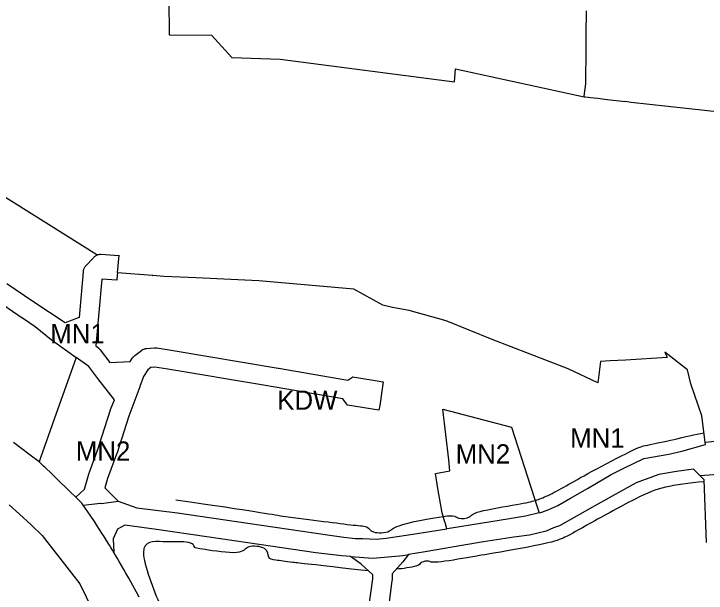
# Model space of a CAD drawing. Extents: x 7413438 to 7416393, y 5541665 to 5544118.
# Drawn here: x 7414826.9 to 7415042.1, y 5542227.9 to 5542408 of the extents above; entities that cross this region are included whole.
import ezdxf

# ---------------------------------------------------------------- set-up
doc = ezdxf.new("R2010")
doc.units = 0
for name, color, linetype in [('linie_rozgraniczajace', 7, 'Continuous'), ('linie_zabudowy_nieprzekraczalne', 7, 'Continuous'), ('oznaczenia_przeznaczen', 7, 'Continuous')]:
    doc.layers.add(name, color=color, linetype=linetype)

msp = doc.modelspace()

# ---------------------------------------------------------------- linework, layer by layer
at = {"layer": 'linie_rozgraniczajace'}
for p, q in [((7414875.1, 5542412.57), (7414875.21, 5542401.44)), ((7415004.88, 5542406.23), (7415004.9, 5542409)), ((7415004.87, 5542404.29), (7415004.88, 5542406.23)), ((7415004.86, 5542402.09), (7415004.87, 5542404.29)), ((7414875.21, 5542401.44), (7414888.35, 5542401.42)), ((7414888.35, 5542401.42), (7414894.65, 5542394.42)), ((7415004.82, 5542397.73), (7415004.86, 5542402.09)), ((7415004.79, 5542393.86), (7415004.82, 5542397.73)), ((7414894.65, 5542394.42), (7414909.73, 5542393.95)), ((7414909.73, 5542393.95), (7414963.87, 5542386.91)), ((7415004.76, 5542389.69), (7415004.79, 5542393.86)), ((7414963.87, 5542386.91), (7414964.25, 5542390.95)), ((7414964.25, 5542390.95), (7415004.16, 5542382.24)), ((7415004.74, 5542386.65), (7415004.76, 5542389.69)), ((7415004.19, 5542382.44), (7415004.74, 5542386.2)), ((7415004.74, 5542386.2), (7415004.74, 5542386.65)), ((7415004.16, 5542382.24), (7415004.17, 5542382.33)), ((7415004.16, 5542382.24), (7415004.54, 5542382.19)), ((7415004.17, 5542382.33), (7415004.19, 5542382.44)), ((7415004.54, 5542382.19), (7415005.47, 5542382.09)), ((7415005.47, 5542382.09), (7415006.12, 5542382.02)), ((7415006.12, 5542382.02), (7415008.5, 5542381.75)), ((7415008.5, 5542381.75), (7415010.65, 5542381.51)), ((7415010.65, 5542381.51), (7415012.33, 5542381.32)), ((7415012.33, 5542381.32), (7415016.12, 5542380.89)), ((7415016.12, 5542380.89), (7415016.95, 5542380.8)), ((7415016.95, 5542380.8), (7415016.95, 5542380.81)), ((7415016.95, 5542380.81), (7415018.81, 5542380.59)), ((7415018.81, 5542380.59), (7415123.31, 5542368.86)), ((7414852.7, 5542333.07), (7414821.41, 5542352.74)), ((7414851.63, 5542332.19), (7414849.22, 5542329.58)), ((7414851.77, 5542332.33), (7414851.63, 5542332.19)), ((7414851.92, 5542332.46), (7414851.77, 5542332.33)), ((7414852.07, 5542332.58), (7414851.92, 5542332.46)), ((7414852.23, 5542332.69), (7414852.07, 5542332.58)), ((7414852.4, 5542332.79), (7414852.23, 5542332.69)), ((7414852.56, 5542332.87), (7414852.4, 5542332.79)), ((7414852.7, 5542333.07), (7414852.56, 5542332.87)), ((7414853.01, 5542333.04), (7414852.7, 5542333.07)), ((7414853.13, 5542333.07), (7414853.01, 5542333.04)), ((7414853.33, 5542333.11), (7414853.13, 5542333.07)), ((7414853.52, 5542333.14), (7414853.33, 5542333.11)), ((7414853.72, 5542333.15), (7414853.52, 5542333.14)), ((7414853.91, 5542333.16), (7414853.72, 5542333.15)), ((7414854.04, 5542333.15), (7414853.91, 5542333.16)), ((7414859.43, 5542332.78), (7414854.04, 5542333.15)), ((7414859.11, 5542327.47), (7414859.62, 5542332.94)), ((7414859.62, 5542332.94), (7414859.43, 5542332.78)), ((7414848.87, 5542329.11), (7414848.77, 5542328.94)), ((7414848.98, 5542329.27), (7414848.87, 5542329.11)), ((7414849.09, 5542329.43), (7414848.98, 5542329.27)), ((7414849.22, 5542329.58), (7414849.09, 5542329.43)), ((7414848.44, 5542327.81), (7414847.18, 5542313.56)), ((7414848.46, 5542328.01), (7414848.44, 5542327.81)), ((7414848.44, 5542327.81), (7414848.44, 5542327.81)), ((7414848.5, 5542328.2), (7414848.46, 5542328.01)), ((7414848.55, 5542328.39), (7414848.5, 5542328.2)), ((7414848.61, 5542328.58), (7414848.55, 5542328.39)), ((7414848.69, 5542328.76), (7414848.61, 5542328.58)), ((7414848.77, 5542328.94), (7414848.69, 5542328.76)), ((7414859.11, 5542327.47), (7414859.05, 5542326.73)), ((7414870.04, 5542326.63), (7414859.11, 5542327.47)), ((7414854.26, 5542325.56), (7414852.43, 5542304.79)), ((7414858.95, 5542325.21), (7414854.26, 5542325.56)), ((7414859.05, 5542326.73), (7414858.95, 5542325.21)), ((7414870.11, 5542326.56), (7414870.04, 5542326.63)), ((7414873.57, 5542326.39), (7414870.11, 5542326.62)), ((7414870.11, 5542326.62), (7414870.11, 5542326.56)), ((7414883.55, 5542325.93), (7414873.57, 5542326.39)), ((7414894.37, 5542325.43), (7414883.55, 5542325.93)), ((7414903.12, 5542325.02), (7414894.37, 5542325.43)), ((7414932.57, 5542322.39), (7414903.12, 5542325.02)), ((7414832.84, 5542318.54), (7414824.76, 5542324.07)), ((7414941.63, 5542317.46), (7414932.57, 5542322.39)), ((7414842.9, 5542311.9), (7414832.84, 5542318.54)), ((7414823.5, 5542317.67), (7414829.55, 5542313.52)), ((7414944.65, 5542316.65), (7414941.63, 5542317.46)), ((7414949.81, 5542315.76), (7414944.65, 5542316.65)), ((7414961.32, 5542312.52), (7414949.81, 5542315.76)), ((7414829.55, 5542313.52), (7414829.57, 5542313.51)), ((7414829.57, 5542313.51), (7414833.56, 5542310.83)), ((7414847.18, 5542313.56), (7414842.9, 5542311.9)), ((7414975.59, 5542306.75), (7414961.32, 5542312.52)), ((7414833.56, 5542310.83), (7414838.56, 5542306.78)), ((7414838.56, 5542306.78), (7414846.32, 5542301.16)), ((7414999.26, 5542297.65), (7414975.59, 5542306.75)), ((7414852.43, 5542304.79), (7414853.34, 5542304.03)), ((7414853.34, 5542304.03), (7414853.45, 5542303.93)), ((7414853.45, 5542303.93), (7414853.59, 5542303.79)), ((7414853.59, 5542303.79), (7414853.72, 5542303.65)), ((7414853.72, 5542303.65), (7414853.8, 5542303.55)), ((7414853.8, 5542303.55), (7414856.79, 5542299.64)), ((7414864.54, 5542301.82), (7414866.6, 5542303.36)), ((7414866.6, 5542303.36), (7414866.63, 5542303.38)), ((7414866.63, 5542303.38), (7414866.79, 5542303.49)), ((7414866.79, 5542303.49), (7414866.96, 5542303.59)), ((7414866.96, 5542303.59), (7414867.13, 5542303.68)), ((7414867.13, 5542303.68), (7414867.32, 5542303.76)), ((7414867.32, 5542303.76), (7414867.5, 5542303.82)), ((7414867.5, 5542303.82), (7414867.69, 5542303.87)), ((7414867.69, 5542303.87), (7414867.88, 5542303.91)), ((7414867.88, 5542303.91), (7414868.08, 5542303.94)), ((7414868.08, 5542303.94), (7414868.12, 5542303.95)), ((7414868.12, 5542303.95), (7414870.62, 5542304.18)), ((7414870.62, 5542304.18), (7414870.78, 5542304.19)), ((7414870.78, 5542304.19), (7414870.97, 5542304.19)), ((7414870.97, 5542304.19), (7414871.17, 5542304.18)), ((7414871.17, 5542304.18), (7414871.37, 5542304.16)), ((7414871.37, 5542304.16), (7414871.4, 5542304.15)), ((7414871.4, 5542304.15), (7414875.8, 5542303.4)), ((7414875.8, 5542303.4), (7414909.11, 5542297.87)), ((7414846.32, 5542301.16), (7414839.48, 5542281.99)), ((7414850.26, 5542298.31), (7414846.32, 5542301.16)), ((7414863.07, 5542299.9), (7414863.83, 5542301.06)), ((7414863.83, 5542301.06), (7414863.89, 5542301.15)), ((7414863.89, 5542301.15), (7414864, 5542301.3)), ((7414864, 5542301.3), (7414864.13, 5542301.45)), ((7414864.13, 5542301.45), (7414864.27, 5542301.59)), ((7414864.27, 5542301.59), (7414864.42, 5542301.72)), ((7414864.42, 5542301.72), (7414864.54, 5542301.82)), ((7415030.04, 5542301.11), (7415017.03, 5542300.33)), ((7415036.34, 5542297.32), (7415029.24, 5542302.83)), ((7415029.24, 5542302.83), (7415030.04, 5542301.11)), ((7414856.79, 5542299.64), (7414863.07, 5542299.9)), ((7415009.3, 5542299.93), (7415008.44, 5542293.25)), ((7415012.27, 5542300.12), (7415009.3, 5542299.93)), ((7415017.02, 5542300.33), (7415012.27, 5542300.12)), ((7415017.03, 5542300.33), (7415017.02, 5542300.33)), ((7414853.37, 5542294.25), (7414850.26, 5542298.31)), ((7414868.56, 5542297.33), (7414867.19, 5542295.24)), ((7414869.52, 5542298.05), (7414868.56, 5542297.33)), ((7414870.79, 5542298.17), (7414869.52, 5542298.05)), ((7414874.8, 5542297.49), (7414870.79, 5542298.17)), ((7414874.81, 5542297.49), (7414874.8, 5542297.49)), ((7414904.56, 5542292.55), (7414874.81, 5542297.49)), ((7414909.11, 5542297.87), (7414909.14, 5542297.87)), ((7414909.14, 5542297.87), (7414930.75, 5542294.06)), ((7415008.44, 5542293.25), (7414999.26, 5542297.65)), ((7415037.38, 5542292.96), (7415036.34, 5542297.32)), ((7414867.19, 5542295.24), (7414866.13, 5542292.11)), ((7414930.75, 5542294.06), (7414932.24, 5542295.11)), ((7414932.24, 5542295.11), (7414941.76, 5542293.57)), ((7414858.16, 5542288.02), (7414853.37, 5542294.25)), ((7414908.12, 5542291.96), (7414904.56, 5542292.55)), ((7414941.76, 5542293.57), (7414941.55, 5542292.17)), ((7415040.82, 5542283.03), (7415037.38, 5542292.96)), ((7414866.09, 5542292.01), (7414862.65, 5542282.94)), ((7414866.1, 5542292.04), (7414866.09, 5542292.01)), ((7414866.13, 5542292.11), (7414866.1, 5542292.04)), ((7414929.18, 5542288.25), (7414908.12, 5542291.96)), ((7414941.55, 5542292.17), (7414940.64, 5542286.24)), ((7414930.61, 5542286.38), (7414929.18, 5542288.25)), ((7414857.01, 5542284.99), (7414858.16, 5542288.02)), ((7414940.42, 5542284.79), (7414930.61, 5542286.38)), ((7414940.64, 5542286.24), (7414940.42, 5542284.79)), ((7414853.48, 5542273.94), (7414856.96, 5542284.84)), ((7414856.96, 5542284.84), (7414857, 5542284.96)), ((7414857, 5542284.96), (7414857.01, 5542284.99)), ((7414962.09, 5542269.38), (7414960.28, 5542285.07)), ((7414960.28, 5542285.07), (7414981.66, 5542279.52)), ((7414839.48, 5542281.99), (7414835.2, 5542269.99)), ((7414862.65, 5542282.94), (7414858.92, 5542271.24)), ((7415041.86, 5542274.87), (7415040.82, 5542283.03)), ((7414981.66, 5542279.52), (7414989.61, 5542254.74)), ((7415041.86, 5542274.87), (7415045.99, 5542275.2)), ((7414831.99, 5542270.81), (7414826.77, 5542274.72)), ((7414850.39, 5542265.47), (7414853.22, 5542273.13)), ((7414853.22, 5542273.13), (7414853.48, 5542273.94)), ((7415034.54, 5542272.07), (7415041.97, 5542274.05)), ((7415041.97, 5542274.05), (7415041.86, 5542274.87)), ((7415041.86, 5542274.87), (7415041.86, 5542274.87)), ((7414858.87, 5542271.11), (7414856.06, 5542263.5)), ((7414858.92, 5542271.24), (7414858.87, 5542271.12)), ((7414858.87, 5542271.12), (7414858.87, 5542271.11)), ((7415022.7, 5542269.71), (7415030.47, 5542271.14)), ((7415030.47, 5542271.14), (7415034.54, 5542272.07)), ((7414834.75, 5542268.74), (7414831.99, 5542270.81)), ((7414835.2, 5542269.99), (7414834.75, 5542268.74)), ((7414835.22, 5542268.29), (7414834.75, 5542268.74)), ((7414962.48, 5542265.92), (7414962.09, 5542269.38)), ((7415016.34, 5542266.59), (7415022.7, 5542269.71)), ((7414835.51, 5542268.02), (7414835.22, 5542268.29)), ((7414836.16, 5542267.39), (7414835.51, 5542268.02)), ((7414836.52, 5542267.06), (7414836.16, 5542267.39)), ((7414837.21, 5542266.4), (7414836.52, 5542267.06)), ((7415012.63, 5542264.77), (7415016.34, 5542266.59)), ((7414838.09, 5542265.56), (7414837.21, 5542266.4)), ((7414840.08, 5542263.61), (7414838.09, 5542265.56)), ((7414848.88, 5542260.25), (7414850.32, 5542265.27)), ((7414850.32, 5542265.27), (7414850.33, 5542265.28)), ((7414850.33, 5542265.28), (7414850.39, 5542265.47)), ((7414850.39, 5542265.47), (7414850.39, 5542265.47)), ((7414957.99, 5542265.07), (7414962.48, 5542265.92)), ((7414958.75, 5542260.43), (7414957.99, 5542265.07)), ((7415008.08, 5542262.12), (7415012.63, 5542264.77)), ((7415027.46, 5542264.78), (7415020.38, 5542262.13)), ((7415032.91, 5542265.73), (7415027.46, 5542264.78)), ((7415038.19, 5542266.47), (7415032.91, 5542265.73)), ((7415039.95, 5542264.67), (7415038.19, 5542266.47)), ((7415040.14, 5542264.49), (7415039.95, 5542264.67)), ((7415040.14, 5542264.49), (7415049.13, 5542265.08)), ((7415041.48, 5542263.15), (7415040.14, 5542264.49)), ((7414841.75, 5542261.98), (7414840.08, 5542263.61)), ((7414856.06, 5542263.5), (7414855.23, 5542260.64)), ((7415042.27, 5542243.65), (7415041.48, 5542263.15)), ((7414842.74, 5542261.02), (7414841.75, 5542261.98)), ((7414843.89, 5542259.9), (7414842.74, 5542261.02)), ((7414846.15, 5542257.69), (7414848.88, 5542260.25)), ((7414855.23, 5542260.64), (7414859.33, 5542256.47)), ((7414960.05, 5542252.81), (7414958.75, 5542260.43)), ((7414999.94, 5542257.37), (7415005.19, 5542260.43)), ((7415005.19, 5542260.43), (7415008.08, 5542262.12)), ((7415020.38, 5542262.13), (7415014.76, 5542259.07)), ((7414844.36, 5542259.44), (7414843.89, 5542259.9)), ((7414844.39, 5542259.4), (7414844.36, 5542259.44)), ((7414846.15, 5542257.69), (7414844.39, 5542259.4)), ((7415014.76, 5542259.07), (7415007.49, 5542255)), ((7414846.15, 5542257.68), (7414846.15, 5542257.69)), ((7414847.42, 5542256.45), (7414846.15, 5542257.68)), ((7414848.09, 5542255.81), (7414847.42, 5542256.45)), ((7414848.45, 5542255.27), (7414853.84, 5542255.83)), ((7414853.84, 5542255.83), (7414854.14, 5542255.78)), ((7414854.14, 5542255.78), (7414859.33, 5542256.47)), ((7414859.33, 5542256.47), (7414865.12, 5542254.43)), ((7414996, 5542255.09), (7414999.94, 5542257.37)), ((7414825.48, 5542255.3), (7414828.68, 5542252.47)), ((7414848.45, 5542255.27), (7414848.09, 5542255.81)), ((7414850.61, 5542252.09), (7414848.44, 5542255.27)), ((7414848.44, 5542255.27), (7414848.45, 5542255.27)), ((7414865.12, 5542254.43), (7414877.8, 5542252.88)), ((7414989.61, 5542254.74), (7414990.22, 5542252.85)), ((7414991.02, 5542253.04), (7414993.18, 5542253.93)), ((7414993.18, 5542253.93), (7414996, 5542255.09)), ((7415007.49, 5542255), (7414996.52, 5542248.82)), ((7414828.68, 5542252.47), (7414832.34, 5542249.09)), ((7414851.95, 5542250.13), (7414850.61, 5542252.09)), ((7414877.8, 5542252.88), (7414899.67, 5542249.68)), ((7414960.92, 5542249.93), (7414960.05, 5542252.81)), ((7414985.96, 5542251.82), (7414981.03, 5542251.02)), ((7414990.22, 5542252.85), (7414985.96, 5542251.82)), ((7414990.22, 5542252.85), (7414991.02, 5542253.04)), ((7414852.37, 5542249.49), (7414851.95, 5542250.13)), ((7414852.45, 5542249.39), (7414852.37, 5542249.49)), ((7414852.84, 5542248.77), (7414852.45, 5542249.39)), ((7414899.67, 5542249.68), (7414925.14, 5542245.95)), ((7414960.96, 5542249.81), (7414960.92, 5542249.93)), ((7414961.54, 5542247.89), (7414960.96, 5542249.81)), ((7414981.03, 5542251.02), (7414963.01, 5542248.12)), ((7414832.34, 5542249.09), (7414835.73, 5542245.84)), ((7414853.37, 5542247.96), (7414852.84, 5542248.77)), ((7414853.73, 5542247.4), (7414853.37, 5542247.96)), ((7414854.09, 5542246.83), (7414853.73, 5542247.4)), ((7414859.17, 5542247.74), (7414857.76, 5542244.77)), ((7414861.44, 5542249.06), (7414859.17, 5542247.74)), ((7414871.28, 5542247.69), (7414861.44, 5542249.06)), ((7414886.91, 5542245.42), (7414871.28, 5542247.69)), ((7414950.93, 5542246.23), (7414961.54, 5542247.89)), ((7414963.01, 5542248.12), (7414961.54, 5542247.89)), ((7414994.63, 5542248.18), (7414992.35, 5542247.17)), ((7414996.52, 5542248.82), (7414994.63, 5542248.18)), ((7414835.73, 5542245.84), (7414844.88, 5542234.08)), ((7414854.42, 5542246.32), (7414854.09, 5542246.83)), ((7414854.74, 5542245.81), (7414854.42, 5542246.32)), ((7414855.09, 5542245.25), (7414854.74, 5542245.81)), ((7414855.42, 5542244.73), (7414855.09, 5542245.25)), ((7414899.63, 5542243.5), (7414886.91, 5542245.42)), ((7414925.14, 5542245.95), (7414929.52, 5542245.31)), ((7414929.52, 5542245.31), (7414933.07, 5542244.92)), ((7414942.69, 5542245.02), (7414950.93, 5542246.23)), ((7414982.31, 5542245.26), (7414972.94, 5542243.87)), ((7414987.2, 5542245.94), (7414982.31, 5542245.26)), ((7414992.35, 5542247.17), (7414987.2, 5542245.94)), ((7414855.69, 5542244.29), (7414855.42, 5542244.73)), ((7414855.96, 5542243.89), (7414855.69, 5542244.29)), ((7414856.25, 5542243.39), (7414855.96, 5542243.89)), ((7414856.64, 5542242.77), (7414856.25, 5542243.39)), ((7414857.76, 5542244.77), (7414857.98, 5542240.56)), ((7414910.25, 5542241.92), (7414899.63, 5542243.5)), ((7414933.07, 5542244.92), (7414935.42, 5542244.83)), ((7414935.42, 5542244.83), (7414939.5, 5542244.67)), ((7414939.5, 5542244.67), (7414942.69, 5542245.02)), ((7414972.94, 5542243.87), (7414966.19, 5542242.71)), ((7414857.08, 5542242.06), (7414856.64, 5542242.77)), ((7414857.55, 5542241.28), (7414857.08, 5542242.06)), ((7414857.98, 5542240.56), (7414857.55, 5542241.28)), ((7414920.74, 5542240.4), (7414910.25, 5542241.92)), ((7414966.19, 5542242.71), (7414954.78, 5542240.73)), ((7414858.51, 5542239.69), (7414857.98, 5542240.56)), ((7414859.15, 5542238.61), (7414858.51, 5542239.69)), ((7414859.7, 5542237.69), (7414859.15, 5542238.61)), ((7414928.86, 5542239.46), (7414920.74, 5542240.4)), ((7414931.57, 5542239.26), (7414928.86, 5542239.46)), ((7414934.91, 5542236.85), (7414931.57, 5542239.26)), ((7414931.57, 5542239.26), (7414938.46, 5542238.74)), ((7414938.46, 5542238.74), (7414942.08, 5542239.02)), ((7414942.08, 5542239.02), (7414947.98, 5542239.61)), ((7414949.64, 5542239.88), (7414947.86, 5542237.58)), ((7414947.98, 5542239.61), (7414949.64, 5542239.88)), ((7414954.78, 5542240.73), (7414949.64, 5542239.88)), ((7414860.41, 5542236.47), (7414859.7, 5542237.69)), ((7414861.13, 5542235.24), (7414860.41, 5542236.47)), ((7414938.49, 5542233.54), (7414934.91, 5542236.85)), ((7414947.86, 5542237.58), (7414944.49, 5542233.86)), ((7414861.76, 5542234.14), (7414861.13, 5542235.24)), ((7414844.88, 5542234.08), (7414847.44, 5542230.8)), ((7414862.67, 5542232.53), (7414861.76, 5542234.14)), ((7414863.3, 5542231.4), (7414862.67, 5542232.53)), ((7414937.19, 5542222.7), (7414938.49, 5542232.36)), ((7414938.49, 5542232.36), (7414938.49, 5542233.54)), ((7414944.49, 5542233.86), (7414944.49, 5542232.13)), ((7414847.44, 5542230.8), (7414854.26, 5542216.67)), ((7414863.95, 5542230.24), (7414863.3, 5542231.4)), ((7414865.06, 5542228.2), (7414863.95, 5542230.24)), ((7414944.46, 5542231.75), (7414943.14, 5542221.91)), ((7414944.47, 5542231.88), (7414944.46, 5542231.75)), ((7414944.48, 5542232.08), (7414944.47, 5542231.88)), ((7414944.49, 5542232.13), (7414944.48, 5542232.08)), ((7414865.9, 5542226.65), (7414865.06, 5542228.2))]:
    msp.add_line(p, q, dxfattribs=at)
at = {"layer": 'linie_zabudowy_nieprzekraczalne'}
for points in [[(7414960.34, 5542251.71), (7414964.14, 5542252.31), (7414964.45, 5542250.62), (7414969.4, 5542251.45), (7414969.11, 5542253.11), (7414985.14, 5542255.7), (7414989.12, 5542256.66), (7414992.58, 5542257.98), (7414998.5, 5542261.13), (7415005.31, 5542265.12), (7415020.46, 5542273.04), (7415022.79, 5542273.76), (7415032.13, 5542275.58), (7415038.67, 5542277.27), (7415041.47, 5542277.68)], [(7415041.47, 5542262.5), (7415036.71, 5542262.19), (7415028.48, 5542260.86), (7415022.01, 5542258.44), (7415002.47, 5542247.55), (7414998.17, 5542245.14), (7414993.94, 5542243.46), (7414976.18, 5542240.27), (7414970.31, 5542239.32), (7414956.55, 5542236.94), (7414956.36, 5542238.08), (7414953.1, 5542237.57), (7414953.3, 5542236.29), (7414947.84, 5542235.44), (7414945.87, 5542235.37)], [(7414877.22, 5542256.93), (7414902.64, 5542253.24), (7414910.15, 5542251.72), (7414923.87, 5542250.15), (7414933.33, 5542248.87), (7414937.48, 5542248.7), (7414937.43, 5542246.57), (7414944.93, 5542246.47), (7414944.83, 5542249.34), (7414960.37, 5542251.71)], [(7414937.05, 5542234.79), (7414918.96, 5542236.83), (7414913.01, 5542237.51), (7414907.9, 5542238.17), (7414905.77, 5542238.49), (7414906.1, 5542242.25), (7414898.74, 5542242.9), (7414898.56, 5542239.57), (7414884.19, 5542241.73), (7414882.79, 5542241.93), (7414882.78, 5542244.08), (7414873.27, 5542243.63), (7414864.14, 5542244.54), (7414873.5, 5542221.1), (7414876.55, 5542214.63), (7414882.51, 5542200.84), (7414883.63, 5542197.05), (7414887.43, 5542190.6), (7414896.19, 5542178.89)]]:
    msp.add_open_spline(points, degree=3, dxfattribs=at)

# ---------------------------------------------------------------- texts
at = {"layer": 'oznaczenia_przeznaczen'}
for s, p in [('MN1', (7414838.23, 5542305.55)), ('KDW', (7414908.8, 5542284.89)), ('MN1', (7414999.84, 5542273.1)), ('MN2', (7414846.2, 5542269.05)), ('MN2', (7414964.26, 5542268.17))]:
    msp.add_text(s, height=6, dxfattribs=at).set_placement(p)

doc.saveas('drawing.dxf')
